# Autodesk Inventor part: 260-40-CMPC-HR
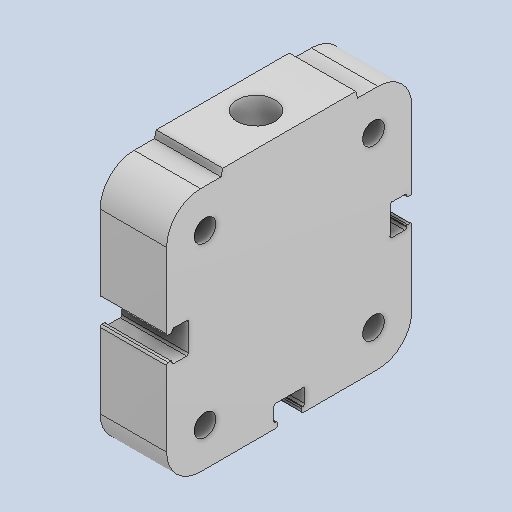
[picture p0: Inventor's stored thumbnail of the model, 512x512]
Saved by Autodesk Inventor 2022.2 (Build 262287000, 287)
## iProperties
Created: 2024-10
Part Number: 260-40-CMPC-HR
Material: Alluminio 6061
Document SubType Name: Modeling
Designer: 18907419
Density: 2.7 g/cm^3
Appearance: Default
Author: 18907419
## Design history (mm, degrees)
feature "Solid1"
node "Solido1"
